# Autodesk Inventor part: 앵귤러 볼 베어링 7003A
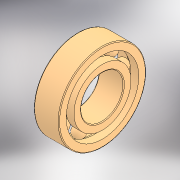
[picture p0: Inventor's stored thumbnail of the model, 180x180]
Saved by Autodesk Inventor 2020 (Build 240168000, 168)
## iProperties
Created: 2024-11
Part Number: 앵귤러 볼 베어링 7003A
Material: 강철, 연강
Description: 앵귤러 콘택트 볼 베어링
Document SubType Name: Modeling
Designer: 1강의실14
Density: 7.85 g/cm^3
Appearance: 기본값
Author: jhkim
Sending System: Autodesk Inventor 2025
Preprocessor: ST-DEVELOPER v20
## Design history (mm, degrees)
feature "Solid1"
feature "Solid1:1"
feature "Solid1:2"
feature "Solid1:3"
feature "Solid1:4"
feature "Solid1:5"
feature "Solid1:6"
feature "Solid1:7"
feature "Solid1:8"
feature "Solid1:9"
feature "Solid1:10"
node "솔리드1"
node "솔리드2"
node "솔리드3"
node "솔리드4"
node "솔리드5"
node "솔리드6"
node "솔리드7"
node "솔리드8"
node "솔리드9"
node "솔리드10"
node "솔리드11"
